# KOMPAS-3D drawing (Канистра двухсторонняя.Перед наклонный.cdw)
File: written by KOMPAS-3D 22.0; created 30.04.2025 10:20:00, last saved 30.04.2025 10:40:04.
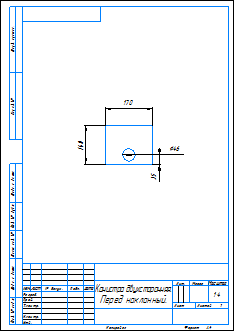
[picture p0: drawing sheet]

Sheet 1: A4, portrait

Document properties: Автор: Admin; Наименование: Канистра двухсторонняя. Перед наклонный; Полное имя файла: D:\28.11.2016\3D модели\Абилимпикс\2025\Канистра двухсторонняя\Канистра двухсторонняя.Перед наклонный.cdw

Title block, sheet 1: Наименование: Канистра двухсторонняя. / Перед наклонный.; scale: 1:4; Количество листов документа: 1; Форматы листов документа: A4; stored path: D:\28.11.2016\3D модели\Абилимпикс\2025\Канистра двухсторонняя\Канистра двухсторонняя.Боковина.cdw

Dimensions and other numbers on the sheet: 170; 140; 35; 46; 1:4; 1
